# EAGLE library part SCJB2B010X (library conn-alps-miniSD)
SCJB2B0101/2 miniSD connector
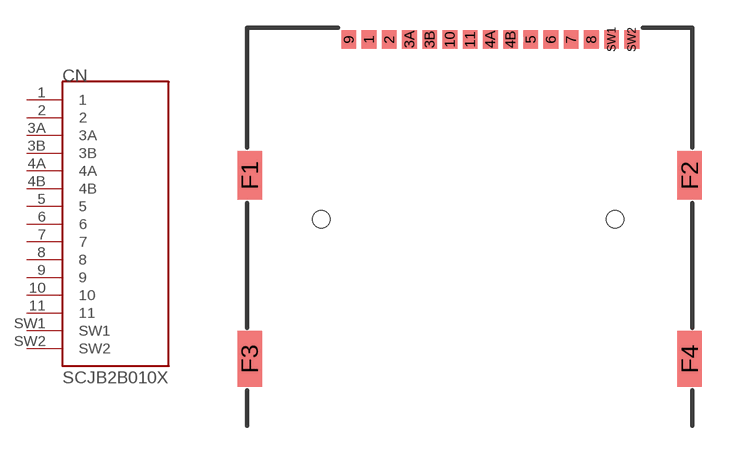
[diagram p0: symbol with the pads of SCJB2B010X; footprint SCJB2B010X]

Designator prefix CN

## SCJB2B010X  [SCJB2B010X]
1  1  pas
2  2  pas
3A  3A  pas
3B  3B  pas
4A  4A  pas
4B  4B  pas
5  5  pas
6  6  pas
7  7  pas
8  8  pas
9  9  pas
10  10  pas
11  11  pas
SW1  SW1  pas
SW2  SW2  pas

## Footprint SCJB2B010X (pad centres in mm)
SCJB2B0101/2 miniSD connector
smd 0.8 x 1: 1 -6.35,0; 2 -5.25,0; 3A -4.15,0; 3B -3.05,0; 4A 0.25,0; 4B 1.35,0; 5 2.45,0; 6 3.55,0; 7 4.65,0; 8 5.75,0; 9 -7.45,0; 10 -1.95,0; 11 -0.85,0; SW1 6.85,0; SW2 7.95,0
smd 1.35 x 2.6: F1 -12.85,-7.4; F2 11.1,-7.4
smd 1.35 x 3: F3 -12.85,-17.4; F4 11.1,-17.4
hole 0.95 at 7.05,-9.8
hole 0.95 at -8.95,-9.8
